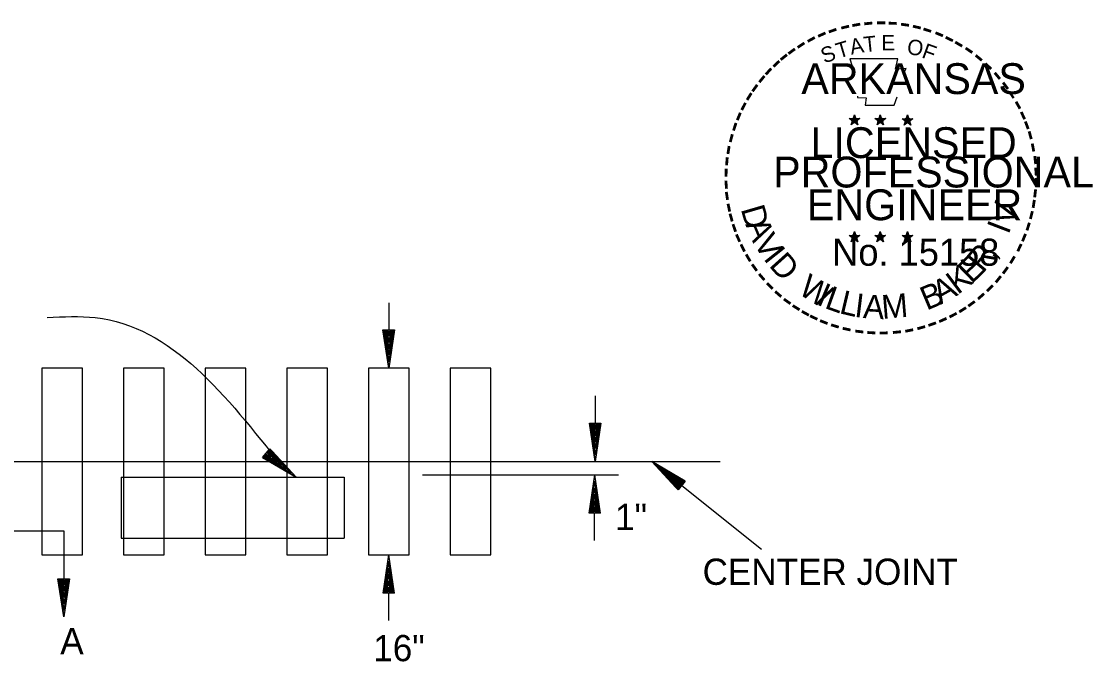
# Model space of a CAD drawing. Extents: x 28704 to 32542, y 50360 to 59122.
# Drawn here: x 32183.6 to 32541.8, y 51126.2 to 51340.2 of the extents above; entities that cross this region are included whole.
import ezdxf

# ---------------------------------------------------------------- set-up
doc = ezdxf.new("R2010")
doc.units = 0
for name, color, linetype in [('Default', 7, 'Continuous'), ('R_Alt Surface', 7, 'Continuous'), ('R_Border Prem', 7, 'Continuous')]:
    doc.layers.add(name, color=color, linetype=linetype)

msp = doc.modelspace()

# ---------------------------------------------------------------- linework, layer by layer
at = {"layer": 'Default'}
for p, q in [((32306.39, 51246.15), (32306.39, 51237.02)), ((32304.53, 51237.02), (32306.45, 51224.21)), ((32304.53, 51237.02), (32308.37, 51237.02)), ((32304.85, 51237.02), (32306.45, 51226.35)), ((32305.17, 51237.02), (32306.45, 51228.55)), ((32305.49, 51237.02), (32306.45, 51230.68)), ((32305.82, 51237.02), (32306.45, 51232.85)), ((32306.15, 51237.02), (32306.45, 51234.99)), ((32308.37, 51237.02), (32306.45, 51224.21)), ((32307.07, 51237.02), (32306.45, 51232.85)), ((32307.72, 51237.02), (32306.45, 51228.55)), ((32308.05, 51237.02), (32306.45, 51226.35)), ((32307.4, 51237.02), (32306.45, 51230.68)), ((32306.75, 51237.02), (32306.45, 51234.99)), ((32375.43, 51214.96), (32375.43, 51205.82)), ((32373.56, 51205.82), (32375.48, 51193.02)), ((32373.56, 51205.82), (32377.4, 51205.82)), ((32373.88, 51205.82), (32375.48, 51195.15)), ((32374.21, 51205.82), (32375.48, 51197.35)), ((32374.53, 51205.82), (32375.48, 51199.49)), ((32374.86, 51205.82), (32375.48, 51201.66)), ((32375.18, 51205.82), (32375.48, 51203.8)), ((32377.4, 51205.82), (32375.48, 51193.02)), ((32376.11, 51205.82), (32375.48, 51201.66)), ((32376.76, 51205.82), (32375.48, 51197.35)), ((32377.08, 51205.82), (32375.48, 51195.15)), ((32376.44, 51205.82), (32375.48, 51199.49)), ((32375.78, 51205.82), (32375.48, 51203.8)), ((32264.21, 51194.34), (32266.6, 51197.34)), ((32266, 51196.58), (32270.36, 51191.89)), ((32266.2, 51196.83), (32272.02, 51190.56)), ((32266.4, 51197.09), (32273.74, 51189.19)), ((32266.6, 51197.34), (32275.42, 51187.85)), ((31789.17, 51193.02), (32417.27, 51193.02)), ((32264.21, 51194.34), (32275.42, 51187.85)), ((32264.41, 51194.59), (32273.74, 51189.19)), ((32264.61, 51194.84), (32272.02, 51190.56)), ((32264.81, 51195.09), (32270.36, 51191.89)), ((32265.02, 51195.35), (32268.66, 51193.24)), ((32265.22, 51195.6), (32266.99, 51194.58)), ((32265.59, 51196.07), (32266.99, 51194.58)), ((32265.8, 51196.33), (32268.66, 51193.24)), ((32394.37, 51193.02), (32431.05, 51163.77)), ((32405.58, 51186.53), (32394.37, 51193.02)), ((32403.19, 51183.53), (32394.37, 51193.02)), ((32405.38, 51186.28), (32396.04, 51191.68)), ((32403.39, 51183.78), (32396.04, 51191.68)), ((32403.59, 51184.04), (32397.76, 51190.31)), ((32405.18, 51186.03), (32397.76, 51190.31)), ((32317.73, 51188.63), (32383.26, 51188.63)), ((32373.4, 51175.83), (32375.32, 51188.63)), ((32373.72, 51175.83), (32375.32, 51186.5)), ((32377.24, 51175.83), (32375.32, 51188.63)), ((32376.92, 51175.83), (32375.32, 51186.5)), ((32404.98, 51185.78), (32399.43, 51188.98)), ((32403.79, 51184.29), (32399.43, 51188.98)), ((32403.99, 51184.54), (32401.13, 51187.63)), ((32404.77, 51185.52), (32401.13, 51187.63)), ((32404.2, 51184.8), (32402.8, 51186.29)), ((32404.57, 51185.27), (32402.8, 51186.29)), ((32405.58, 51186.53), (32403.19, 51183.53)), ((32374.05, 51175.83), (32375.32, 51184.29)), ((32376.59, 51175.83), (32375.32, 51184.29)), ((32374.37, 51175.83), (32375.32, 51182.16)), ((32374.69, 51175.83), (32375.32, 51179.99)), ((32376.27, 51175.83), (32375.32, 51182.16)), ((32375.94, 51175.83), (32375.32, 51179.99)), ((32377.24, 51175.83), (32373.4, 51175.83)), ((32375.02, 51175.83), (32375.32, 51177.85)), ((32375.26, 51166.69), (32375.26, 51175.83)), ((32375.62, 51175.83), (32375.32, 51177.85)), ((32156.39, 51169.84), (32197.71, 51169.84)), ((32197.71, 51169.84), (32197.71, 51153.87)), ((32304.53, 51149.01), (32306.45, 51161.82)), ((32308.37, 51149.01), (32306.45, 51161.82)), ((32304.85, 51149.01), (32306.45, 51159.68)), ((32305.17, 51149.01), (32306.45, 51157.48)), ((32308.05, 51149.01), (32306.45, 51159.68)), ((32307.72, 51149.01), (32306.45, 51157.48)), ((32195.85, 51153.87), (32197.77, 51141.07)), ((32195.85, 51153.87), (32199.69, 51153.87)), ((32196.17, 51153.87), (32197.77, 51143.21)), ((32196.49, 51153.87), (32197.77, 51145.41)), ((32196.82, 51153.87), (32197.77, 51147.54)), ((32197.15, 51153.87), (32197.77, 51149.71)), ((32197.47, 51153.87), (32197.77, 51151.85)), ((32199.69, 51153.87), (32197.77, 51141.07)), ((32198.4, 51153.87), (32197.77, 51149.71)), ((32199.04, 51153.87), (32197.77, 51145.41)), ((32199.37, 51153.87), (32197.77, 51143.21)), ((32198.72, 51153.87), (32197.77, 51147.54)), ((32198.07, 51153.87), (32197.77, 51151.85)), ((32305.49, 51149.01), (32306.45, 51155.35)), ((32307.4, 51149.01), (32306.45, 51155.35)), ((32305.82, 51149.01), (32306.45, 51153.18)), ((32306.15, 51149.01), (32306.45, 51151.04)), ((32307.07, 51149.01), (32306.45, 51153.18)), ((32306.75, 51149.01), (32306.45, 51151.04)), ((32308.37, 51149.01), (32304.53, 51149.01)), ((32306.39, 51139.88), (32306.39, 51149.01))]:
    msp.add_line(p, q, dxfattribs=at)
for points in [[(32190.39, 51224.21), (32190.39, 51161.82), (32204.04, 51161.82), (32204.04, 51224.21)], [(32217.7, 51224.21), (32217.7, 51161.82), (32231.35, 51161.82), (32231.35, 51224.21)], [(32245.01, 51224.21), (32245.01, 51161.82), (32258.66, 51161.82), (32258.66, 51224.21)], [(32272.31, 51224.21), (32272.31, 51161.82), (32285.97, 51161.82), (32285.97, 51224.21)], [(32299.62, 51224.21), (32299.62, 51161.82), (32313.27, 51161.82), (32313.27, 51224.21)], [(32326.93, 51224.21), (32326.93, 51161.82), (32340.58, 51161.82), (32340.58, 51224.21)]]:
    msp.add_lwpolyline(points, close=True, dxfattribs=at)
msp.add_spline([(32192.18, 51241.17), (32208.26, 51241.17), (32270.53, 51191.56)], degree=3, dxfattribs=at)
at = {"layer": 'R_Alt Surface'}
for p, q in [((32216.95, 51187.85), (32216.95, 51167.45)), ((32216.95, 51187.85), (32291.52, 51187.85)), ((32291.52, 51187.85), (32291.52, 51167.45)), ((32216.95, 51167.45), (32291.52, 51167.45))]:
    msp.add_line(p, q, dxfattribs=at)
for points in [[(32304.46, 51237.02), (32308.32, 51237.02), (32306.45, 51224.21)], [(32373.5, 51205.82), (32377.35, 51205.82), (32375.48, 51193.02)], [(32265.18, 51193.79), (32267.38, 51196.54), (32275.42, 51187.85)], [(32404.6, 51187.08), (32402.41, 51184.33), (32394.37, 51193.02)], [(32195.78, 51153.87), (32199.64, 51153.87), (32197.77, 51141.07)]]:
    msp.add_lwpolyline(points, close=True, dxfattribs=at)
at = {"layer": 'R_Border Prem'}
for p, q in [((32460.41, 51307.69), (32462.21, 51307.11)), ((32460.41, 51307.69), (32461.72, 51307.46)), ((32460.41, 51307.69), (32461.63, 51307.06)), ((32462.21, 51309), (32462, 51307.7)), ((32462.21, 51307.11), (32462.21, 51309)), ((32462.21, 51309), (32462.46, 51307.71)), ((32464, 51307.69), (32462.21, 51307.11)), ((32464, 51307.69), (32462.53, 51307.43)), ((32464, 51307.69), (32462.95, 51307.16)), ((32469.02, 51307.69), (32470.82, 51307.11)), ((32469.02, 51307.69), (32470.33, 51307.46)), ((32469.02, 51307.69), (32470.25, 51307.06)), ((32470.82, 51309), (32470.61, 51307.7)), ((32470.82, 51307.11), (32470.82, 51309)), ((32470.82, 51309), (32471.08, 51307.71)), ((32472.61, 51307.69), (32470.82, 51307.11)), ((32472.61, 51307.69), (32471.14, 51307.43)), ((32472.61, 51307.69), (32471.56, 51307.16)), ((32478.12, 51307.63), (32479.92, 51307.05)), ((32478.12, 51307.63), (32479.42, 51307.39)), ((32478.12, 51307.63), (32479.34, 51307)), ((32479.92, 51308.94), (32479.71, 51307.64)), ((32479.92, 51307.05), (32479.92, 51308.94)), ((32479.92, 51308.94), (32480.17, 51307.65)), ((32481.71, 51307.63), (32479.92, 51307.05)), ((32481.71, 51307.63), (32480.23, 51307.37)), ((32481.71, 51307.63), (32480.66, 51307.1)), ((32461.1, 51305.58), (32462.21, 51307.11)), ((32461.1, 51305.58), (32461.75, 51306.84)), ((32461.1, 51305.58), (32462.2, 51306.7)), ((32463.31, 51305.58), (32462.2, 51306.69)), ((32463.31, 51305.58), (32462.21, 51307.11)), ((32463.31, 51305.58), (32462.6, 51307.08)), ((32469.71, 51305.58), (32470.82, 51307.11)), ((32469.71, 51305.58), (32470.36, 51306.84)), ((32469.71, 51305.58), (32470.81, 51306.7)), ((32471.92, 51305.58), (32470.81, 51306.69)), ((32471.92, 51305.58), (32470.82, 51307.11)), ((32471.92, 51305.58), (32471.21, 51307.08)), ((32478.8, 51305.52), (32479.92, 51307.05)), ((32478.8, 51305.52), (32479.45, 51306.78)), ((32478.8, 51305.52), (32479.91, 51306.64)), ((32481.02, 51305.52), (32479.91, 51306.63)), ((32481.02, 51305.52), (32479.92, 51307.05)), ((32481.02, 51305.52), (32480.31, 51307.02)), ((32460.39, 51268.64), (32462.19, 51268.07)), ((32460.39, 51268.64), (32461.7, 51268.41)), ((32460.39, 51268.64), (32461.61, 51268.01)), ((32462.19, 51269.95), (32461.98, 51268.65)), ((32462.19, 51268.07), (32462.19, 51269.95)), ((32462.19, 51269.95), (32462.44, 51268.66)), ((32463.98, 51268.64), (32462.19, 51268.07)), ((32463.98, 51268.64), (32462.51, 51268.39)), ((32463.98, 51268.64), (32462.93, 51268.11)), ((32469, 51268.64), (32470.8, 51268.07)), ((32469, 51268.64), (32470.3, 51268.41)), ((32469, 51268.64), (32470.22, 51268.01)), ((32470.8, 51269.95), (32470.59, 51268.65)), ((32470.8, 51268.07), (32470.8, 51269.95)), ((32470.8, 51269.95), (32471.05, 51268.66)), ((32472.59, 51268.64), (32470.8, 51268.07)), ((32472.59, 51268.64), (32471.11, 51268.39)), ((32472.59, 51268.64), (32471.53, 51268.11)), ((32478.11, 51268.59), (32479.91, 51268.02)), ((32478.11, 51268.59), (32479.41, 51268.36)), ((32478.11, 51268.59), (32479.33, 51267.96)), ((32479.91, 51269.9), (32479.7, 51268.6)), ((32479.91, 51268.02), (32479.91, 51269.9)), ((32479.91, 51269.9), (32480.16, 51268.61)), ((32481.7, 51268.59), (32479.91, 51268.02)), ((32481.7, 51268.59), (32480.22, 51268.33)), ((32481.7, 51268.59), (32480.65, 51268.06)), ((32461.08, 51266.54), (32462.19, 51268.07)), ((32461.08, 51266.54), (32461.73, 51267.79)), ((32461.08, 51266.54), (32462.18, 51267.65)), ((32463.29, 51266.54), (32462.18, 51267.64)), ((32463.29, 51266.54), (32462.19, 51268.07)), ((32463.29, 51266.54), (32462.58, 51268.04)), ((32469.68, 51266.54), (32470.8, 51268.07)), ((32469.68, 51266.54), (32470.33, 51267.79)), ((32469.68, 51266.54), (32470.79, 51267.65)), ((32471.9, 51266.54), (32470.79, 51267.64)), ((32471.9, 51266.54), (32470.8, 51268.07)), ((32471.9, 51266.54), (32471.19, 51268.04)), ((32478.79, 51266.48), (32479.91, 51268.02)), ((32478.79, 51266.48), (32479.44, 51267.74)), ((32478.79, 51266.48), (32479.9, 51267.6)), ((32481.01, 51266.48), (32479.9, 51267.59)), ((32481.01, 51266.48), (32479.91, 51268.02)), ((32481.01, 51266.48), (32480.3, 51267.98))]:
    msp.add_line(p, q, dxfattribs=at)
for points in [[(32460.62, 51327.68), (32462.01, 51323.42)], [(32478.73, 51322.93), (32479.46, 51324.39), (32475.93, 51324.27), (32476.69, 51327.68), (32460.62, 51327.68)], [(32463.16, 51315.19), (32463.16, 51314.74), (32466.06, 51314.64), (32465.78, 51312.2), (32475.43, 51312.2), (32476.46, 51314.97)], [(32462.21, 51309), (32463.31, 51305.58), (32460.41, 51307.69), (32464, 51307.69), (32461.1, 51305.58), (32462.21, 51309)], [(32470.82, 51309), (32471.92, 51305.58), (32469.02, 51307.69), (32472.61, 51307.69), (32469.71, 51305.58), (32470.82, 51309)], [(32479.92, 51308.94), (32481.02, 51305.52), (32478.12, 51307.63), (32481.71, 51307.63), (32478.8, 51305.52), (32479.92, 51308.94)], [(32462.19, 51269.95), (32463.29, 51266.54), (32460.39, 51268.64), (32463.98, 51268.64), (32461.08, 51266.54), (32462.19, 51269.95)], [(32470.8, 51269.95), (32471.9, 51266.54), (32469, 51268.64), (32472.59, 51268.64), (32469.68, 51266.54), (32470.8, 51269.95)], [(32479.91, 51269.9), (32481.01, 51266.48), (32478.11, 51268.59), (32481.7, 51268.59), (32478.79, 51266.48), (32479.91, 51269.9)]]:
    msp.add_lwpolyline(points, dxfattribs=at)
for centre, radius in [((32462.21, 51307.11), 0.888), ((32462.21, 51307.11), 0.745), ((32462.21, 51307.11), 0.597), ((32470.82, 51307.11), 0.888), ((32470.82, 51307.11), 0.745), ((32470.82, 51307.11), 0.597), ((32479.91, 51307.05), 0.888), ((32479.91, 51307.05), 0.745), ((32479.91, 51307.05), 0.597), ((32462.21, 51307.11), 0.511), ((32462.21, 51307.11), 0.385), ((32462.21, 51307.11), 0.255), ((32462.21, 51307.11), 0.153), ((32470.82, 51307.11), 0.511), ((32470.82, 51307.11), 0.385), ((32470.82, 51307.11), 0.255), ((32470.82, 51307.11), 0.153), ((32479.91, 51307.05), 0.511), ((32479.91, 51307.05), 0.385), ((32479.91, 51307.05), 0.255), ((32479.91, 51307.05), 0.153), ((32462.19, 51268.06), 0.888), ((32462.19, 51268.06), 0.745), ((32462.19, 51268.06), 0.597), ((32462.19, 51268.06), 0.511), ((32462.19, 51268.06), 0.385), ((32462.19, 51268.06), 0.255), ((32470.79, 51268.06), 0.888), ((32470.79, 51268.06), 0.745), ((32470.79, 51268.06), 0.597), ((32470.79, 51268.06), 0.511), ((32470.79, 51268.06), 0.385), ((32470.79, 51268.06), 0.255), ((32479.9, 51268.01), 0.888), ((32479.9, 51268.01), 0.745), ((32479.9, 51268.01), 0.597), ((32479.9, 51268.01), 0.511), ((32479.9, 51268.01), 0.385), ((32479.9, 51268.01), 0.255), ((32462.19, 51268.06), 0.153), ((32470.79, 51268.06), 0.153), ((32479.9, 51268.01), 0.153)]:
    msp.add_circle(centre, radius, dxfattribs=at)

# ---------------------------------------------------------------- texts
at = {"layer": 'Default'}
for s, height, p in [('1"', 8.771, (32382.11, 51170.14)), ('CENTER JOINT', 8.7711, (32411.38, 51151.82)), ('A', 8.77, (32196.56, 51128.64)), ('16"', 8.771, (32301.23, 51126.29))]:
    msp.add_text(s, height=height, dxfattribs=at).set_placement(p)
at = {"layer": 'R_Border Prem'}
for s, height, rotation, p in [('-', 8.25, 5.8968, (32465.29, 51336.14)), ('-', 8.25, 0.1862, (32469.27, 51336.51)), ('-', 8.25, 357.743, (32473, 51336.44)), ('-', 8.25, 24.3072, (32450.9, 51332.11)), ('-', 8.25, 19.1761, (32454.17, 51333.49)), ('-', 8.25, 13.6302, (32458.03, 51334.74)), ('-', 8.25, 10.2193, (32461.53, 51335.57)), ('-', 8.25, 352.1617, (32476.83, 51336.15)), ('-', 8.25, 347.2049, (32480.54, 51335.57)), ('-', 8.25, 342.3362, (32483.82, 51334.77)), ('-', 8.25, 337.8551, (32487.61, 51333.62)), ('-', 8.25, 34.0636, (32444.56, 51328.56)), ('-', 8.25, 28.7918, (32447.63, 51330.47)), ('T', 5.16, 16.4036, (32456.85, 51327.73)), ('A', 5.16, 11.2132, (32461.11, 51329.02)), ('T', 5.16, 6.0228, (32465.49, 51329.88)), ('E', 5.16, 0.8323, (32471.19, 51330.45)), ('O', 5.16, 350.4515, (32479.46, 51329.36)), ('F', 5.16, 340.0707, (32484.38, 51328.19)), ('-', 8.25, 334.1211, (32490.86, 51332.22)), ('-', 8.25, 329.6409, (32493.84, 51330.76)), ('-', 8.25, 38.9507, (32439.12, 51324.58)), ('-', 8.25, 36.2317, (32441.58, 51326.53)), ('S', 5.16, 21.594, (32452.14, 51326.02)), ('-', 8.25, 325.8627, (32497.16, 51328.9)), ('-', 8.25, 320.5297, (32500.3, 51326.7)), ('-', 8.25, 42.9622, (32436.89, 51322.43)), ('-', 8.25, 315.5786, (32503.39, 51324.19)), ('-', 8.25, 50.6142, (32432.5, 51317.46)), ('-', 8.25, 48.4231, (32434.58, 51319.96)), ('-', 8.25, 309.8797, (32506.33, 51321.35)), ('-', 8.25, 54.2325, (32430.37, 51314.53)), ('-', 8.25, 306.6522, (32509.03, 51318.25)), ('-', 8.25, 58.0706, (32428.69, 51311.82)), ('-', 7.22, 303.6753, (32511.54, 51315.32)), ('-', 8.25, 62.8713, (32427.08, 51308.65)), ('-', 8.25, 299.6684, (32513.19, 51312.19)), ('-', 8.25, 67.7743, (32425.75, 51305.5)), ('-', 8.25, 294.6628, (32514.86, 51309.03)), ('-', 8.25, 72.3945, (32424.62, 51302.25)), ('-', 8.25, 290.5728, (32516.18, 51306.06)), ('-', 8.25, 75.461, (32423.6, 51298.57)), ('-', 8.25, 285.1233, (32517.39, 51303.07)), ('-', 8.25, 81.2013, (32422.92, 51294.89)), ('-', 8.25, 280.5493, (32518.42, 51299.24)), ('-', 8.25, 85.1863, (32422.53, 51291.33)), ('-', 8.25, 276.5962, (32519.25, 51295.28)), ('-', 8.25, 89.0622, (32422.4, 51287.72)), ('-', 8.25, 274.3301, (32519.56, 51291.56)), ('-', 8.25, 94.1959, (32422.58, 51283.98)), ('-', 8.25, 269.9407, (32519.74, 51288.3)), ('-', 8.25, 98.9479, (32422.95, 51280.54)), ('-', 8.25, 263.5172, (32519.64, 51284.87)), ('-', 8.25, 101.7149, (32423.65, 51276.76)), ('V', 7.94, 72.6573, (32514.81, 51271.49)), ('-', 8.25, 260.9953, (32519.27, 51281.49)), ('-', 8.25, 105.4578, (32424.48, 51273.69)), ('D', 7.94, 286.2848, (32424.1, 51277.47)), ('-', 8.25, 255.7626, (32518.71, 51278)), ('-', 8.25, 109.0874, (32425.59, 51270.44)), ('A', 7.94, 292.7835, (32425.61, 51272.31)), ('I', 7.94, 69.0301, (32513.67, 51268.71)), ('-', 8.25, 252.8681, (32517.77, 51274.29)), ('-', 8.25, 114.0643, (32426.9, 51267.37)), ('V', 7.94, 300.7936, (32428.26, 51266.23)), ('-', 8.25, 247.8887, (32516.62, 51270.81)), ('-', 8.25, 115.7289, (32428.47, 51264.18)), ('I', 7.94, 308.3502, (32431.52, 51260.88)), ('R', 7.94, 50.3651, (32505.16, 51255.87)), ('-', 8.25, 244.6197, (32515.27, 51267.57)), ('-', 8.25, 120.4471, (32430.31, 51261.16)), ('D', 7.94, 311.9774, (32433.32, 51258.48)), ('E', 7.94, 44.0175, (32501.37, 51252.23)), (',', 7.94, 57.4684, (32508.89, 51260.43)), ('-', 8.25, 239.0712, (32513.24, 51263.69)), ('-', 8.25, 125.8934, (32432.39, 51258.26)), ('K', 7.94, 36.9143, (32496.69, 51248.67)), ('-', 8.25, 233.8452, (32511.17, 51260.33)), ('-', 8.25, 130.7181, (32434.77, 51255.42)), ('W', 7.94, 328.0731, (32443.01, 51249.37)), ('A', 7.94, 28.9042, (32490.92, 51245.38)), ('-', 8.25, 231.2538, (32508.95, 51257.41)), ('-', 8.25, 134.2238, (32437.44, 51252.61)), ('I', 7.94, 336.6877, (32449.13, 51245.71)), ('L', 7.94, 340.3149, (32451.86, 51244.45)), ('B', 7.94, 22.8589, (32486.3, 51243.46)), ('-', 8.25, 225.7653, (32506.48, 51254.5)), ('-', 8.25, 138.9338, (32440.15, 51250.22)), ('-', 8.25, 144.6463, (32443.01, 51248.12)), ('L', 7.94, 346.6625, (32456.81, 51242.68)), ('I', 7.94, 353.0101, (32461.93, 51241.46)), ('A', 7.94, 356.6373, (32464.9, 51241.02)), ('M', 7.94, 4.6473, (32471.52, 51240.72)), ('-', 8.25, 215.7363, (32500.96, 51249.44)), ('-', 8.25, 221.0851, (32503.79, 51251.88)), ('-', 8.25, 148.0898, (32445.91, 51246.21)), ('-', 8.25, 151.5704, (32448.89, 51244.53)), ('-', 8.25, 212.2491, (32498.21, 51247.45)), ('-', 8.25, 154.6002, (32451.58, 51243.26)), ('-', 8.25, 158.5612, (32454.8, 51241.95)), ('-', 8.25, 199.4643, (32488.86, 51242.59)), ('-', 8.25, 204.2516, (32492.11, 51244.02)), ('-', 8.25, 207.3568, (32495.33, 51245.66)), ('-', 8.25, 162.7983, (32458.34, 51240.85)), ('-', 8.25, 167.5555, (32462.03, 51240.01)), ('-', 8.25, 173.1155, (32466.01, 51239.44)), ('-', 8.25, 176.5183, (32469.87, 51239.17)), ('-', 8.25, 181.5918, (32473.7, 51239.26)), ('-', 8.25, 185.8167, (32477.88, 51239.66)), ('-', 8.25, 191.2858, (32481.67, 51240.34)), ('-', 8.25, 195.4743, (32485.43, 51241.36))]:
    msp.add_text(s, height=height, rotation=rotation, dxfattribs=at).set_placement(p)
for s, height, p in [('ARKANSAS', 10.312, (32444.4, 51315.89)), ('LICENSED', 10.312, (32447.48, 51294.49)), ('PROFESSIONAL', 10.3125, (32434.98, 51284.67)), ('ENGINEER', 10.312, (32446.26, 51273.72)), ('No. 15158', 9.06, (32454.72, 51258.5)), ('AAMU', 0.000103, (32470.45, 51240.69))]:
    msp.add_text(s, height=height, dxfattribs=at).set_placement(p)

doc.saveas('drawing.dxf')
